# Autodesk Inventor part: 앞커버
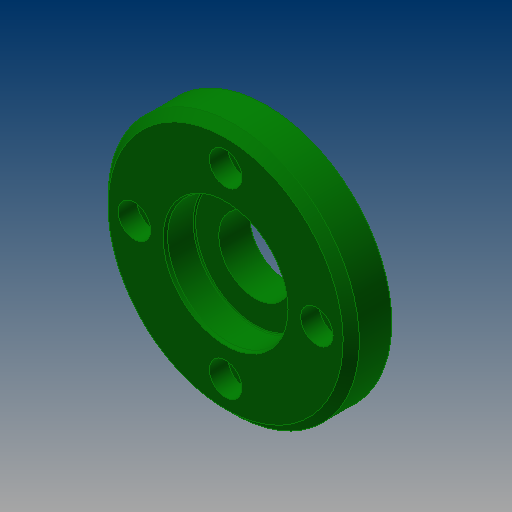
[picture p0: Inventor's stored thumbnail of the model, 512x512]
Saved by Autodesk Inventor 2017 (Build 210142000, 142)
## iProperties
Created: 2015-09
Part Number: 앞커버
Material: 알루미늄 6061
Document SubType Name: Modeling
Designer: mduedu
Density: 1 g/cm^3
Appearance: 진녹색
Author: mduedu
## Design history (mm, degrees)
sketch "스케치1"
  geometry: L1 (0, 7.5)-(0, -7.5); L2 (0, 7.5)-(31, 7.5); L3 (31, 7.5)-(31, -2.5); L4 (31, -2.5)-(17.5, -2.5); L5 (17.5, -2.5)-(17.5, -7.5); L6 (17.5, -7.5)-(0, -7.5); 2 further points
  constraints: 12 end point, 2 parallel, 2 perpendicular, 1 coincident, 1 horizontal, 1 midpoint, 1 vertical
  dimensions: "d0" = 15 distance of L1.start L1.end; "d1" = 62 diameter of L3 L1; "d2" = 35 diameter of L5 L1; "d3" = 10 distance of L2.end L3.end
revolve "회전1" sketch "스케치1" stored, may be unused: angle "d4" = 90 deg
hole "구멍1" diameter "d7" = 30; stored, may be unused: countersink angle "d11" = 90 deg, drill point angle "d13" = 0 deg; dims "d5" = 10, "d6" = 10, "d8" = 6, "d9" = 4, "d10" = 2, "d12" = 7.3
hole "구멍2" diameter "d16" = 18; stored, may be unused: countersink angle "d20" = 90 deg, drill point angle "d22" = 0 deg; dims "d14" = 10, "d15" = 10, "d17" = 6, "d18" = 4, "d19" = 2, "d21" = 7.3
chamfer "모따기1" distance "d23" = 2; stored, may be unused: second distance "d24" = 2, angle "d25" = 45 deg
chamfer "모따기2" distance "d26" = 0.7; stored, may be unused: second distance "d27" = 2, angle "d28" = 30 deg
fillet "모깎기1" dims "d29" = 0.3
sketch "스케치2" dims "d30" = 45
  geometry: 6 further points
  constraints: 2 vertical alignment, 1 coincident, 7 other
  dimensions: "d34" = 360 deg dimension on point (0, 0) point (0, 22.5) (derived)
sketch "스케치3"
  geometry: 4 further points
hole "구멍3" sketch "스케치3" at (0, 22.5), (-22.5, 0), (22.5, 0), (0, -22.5) diameter "d36" = 4.5; stored, may be unused: countersink angle "d40" = 90 deg, drill point angle "d42" = 0 deg; dims "d37" = 6, "d38" = 8, "d39" = 4.6, "d41" = 8
chamfer "모따기3" distance "d43" = 1; stored, may be unused: second distance "d44" = 2, angle "d45" = 45 deg
node "솔리드1"
